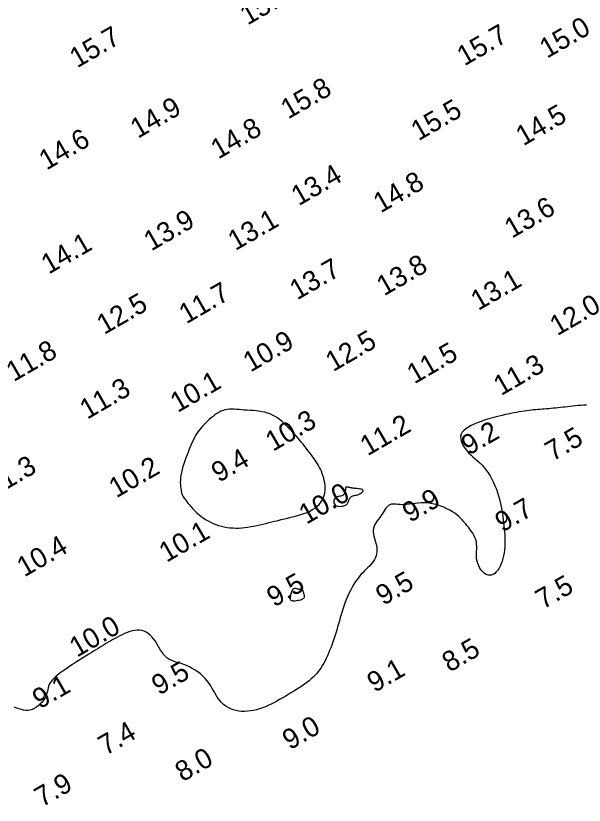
# Model space of a CAD drawing. Extents: x 3024098 to 3056816, y 418252 to 509144.
# Drawn here: x 3035040.4 to 3035182.6, y 418904.8 to 419102.3 of the extents above; entities that cross this region are included whole.
import ezdxf

# ---------------------------------------------------------------- set-up
doc = ezdxf.new("R2010")
doc.units = 0
doc.layers.add('V-CHAN-CONT-EL10', color=7, linetype='Continuous')
doc.layers.add('V-TOPO-SOUN-0911', color=7, linetype='Continuous')

msp = doc.modelspace()

# ---------------------------------------------------------------- linework, layer by layer
at = {"layer": 'V-CHAN-CONT-EL10'}
msp.add_lwpolyline([(3035183.1, 419004.9), (3035182.4, 419004.89), (3035181.71, 419004.86), (3035181.03, 419004.82), (3035180.37, 419004.76), (3035179.72, 419004.68), (3035179.08, 419004.61), (3035178.45, 419004.53), (3035177.83, 419004.45), (3035177.21, 419004.37), (3035176.61, 419004.3), (3035176.01, 419004.23), (3035175.41, 419004.18), (3035174.83, 419004.12), (3035174.25, 419004.08), (3035173.69, 419004.03), (3035173.13, 419003.98), (3035172.58, 419003.94), (3035172.04, 419003.9), (3035171.51, 419003.86), (3035170.98, 419003.81), (3035170.45, 419003.76), (3035169.91, 419003.71), (3035169.36, 419003.65), (3035168.8, 419003.59), (3035168.21, 419003.51), (3035167.61, 419003.42), (3035166.98, 419003.33), (3035166.33, 419003.23), (3035165.65, 419003.11), (3035164.96, 419002.98), (3035164.26, 419002.85), (3035163.54, 419002.7), (3035162.8, 419002.54), (3035162.05, 419002.36), (3035161.29, 419002.18), (3035160.52, 419001.98), (3035159.74, 419001.77), (3035158.96, 419001.54), (3035158.17, 419001.3), (3035157.38, 419001.04), (3035156.58, 419000.76), (3035155.79, 419000.46), (3035155.02, 419000.14), (3035154.28, 418999.8), (3035153.6, 418999.43), (3035152.99, 418999.03), (3035152.48, 418998.6), (3035152.07, 418998.14), (3035151.8, 418997.64), (3035151.67, 418997.1), (3035151.68, 418996.53), (3035151.8, 418995.94), (3035152.02, 418995.34), (3035152.34, 418994.74), (3035152.73, 418994.14), (3035153.18, 418993.56), (3035153.67, 418993), (3035154.2, 418992.47), (3035154.75, 418991.96), (3035155.31, 418991.46), (3035155.88, 418990.96), (3035156.45, 418990.44), (3035157.01, 418989.89), (3035157.56, 418989.3), (3035158.09, 418988.66), (3035158.58, 418987.96), (3035159.05, 418987.21), (3035159.49, 418986.41), (3035159.89, 418985.59), (3035160.26, 418984.75), (3035160.6, 418983.9), (3035160.9, 418983.05), (3035161.16, 418982.23), (3035161.39, 418981.43), (3035161.59, 418980.66), (3035161.75, 418979.9), (3035161.9, 418979.16), (3035162.02, 418978.43), (3035162.13, 418977.7), (3035162.23, 418976.98), (3035162.32, 418976.24), (3035162.42, 418975.5), (3035162.5, 418974.75), (3035162.58, 418974), (3035162.65, 418973.24), (3035162.71, 418972.47), (3035162.74, 418971.7), (3035162.76, 418970.94), (3035162.75, 418970.17), (3035162.71, 418969.41), (3035162.64, 418968.66), (3035162.54, 418967.92), (3035162.41, 418967.2), (3035162.25, 418966.51), (3035162.06, 418965.84), (3035161.83, 418965.22), (3035161.56, 418964.63), (3035161.27, 418964.09), (3035160.94, 418963.6), (3035160.58, 418963.18), (3035160.2, 418962.83), (3035159.8, 418962.57), (3035159.39, 418962.4), (3035158.96, 418962.34), (3035158.52, 418962.38), (3035158.08, 418962.54), (3035157.65, 418962.82), (3035157.23, 418963.18), (3035156.84, 418963.62), (3035156.48, 418964.13), (3035156.18, 418964.68), (3035155.93, 418965.27), (3035155.76, 418965.87), (3035155.66, 418966.48), (3035155.62, 418967.1), (3035155.62, 418967.71), (3035155.65, 418968.32), (3035155.68, 418968.93), (3035155.69, 418969.53), (3035155.67, 418970.12), (3035155.6, 418970.69), (3035155.45, 418971.26), (3035155.25, 418971.81), (3035154.99, 418972.34), (3035154.68, 418972.86), (3035154.34, 418973.38), (3035153.98, 418973.87), (3035153.61, 418974.36), (3035153.23, 418974.84), (3035152.85, 418975.3), (3035152.46, 418975.75), (3035152.07, 418976.2), (3035151.65, 418976.63), (3035151.21, 418977.05), (3035150.72, 418977.46), (3035150.19, 418977.87), (3035149.6, 418978.26), (3035148.94, 418978.65), (3035148.23, 418979.01), (3035147.48, 418979.36), (3035146.69, 418979.67), (3035145.88, 418979.94), (3035145.05, 418980.16), (3035144.22, 418980.33), (3035143.4, 418980.44), (3035142.59, 418980.48), (3035141.8, 418980.46), (3035141.04, 418980.4), (3035140.29, 418980.31), (3035139.58, 418980.22), (3035138.9, 418980.12), (3035138.25, 418980.04), (3035137.63, 418980), (3035137.05, 418980), (3035136.5, 418980.04), (3035136, 418980.08), (3035135.52, 418980.13), (3035135.08, 418980.16), (3035134.68, 418980.16), (3035134.3, 418980.11), (3035133.96, 418980), (3035133.64, 418979.81), (3035133.35, 418979.55), (3035133.08, 418979.24), (3035132.82, 418978.88), (3035132.56, 418978.48), (3035132.3, 418978.06), (3035132.03, 418977.63), (3035131.75, 418977.2), (3035131.44, 418976.77), (3035131.12, 418976.35), (3035130.81, 418975.93), (3035130.51, 418975.51), (3035130.25, 418975.08), (3035130.03, 418974.63), (3035129.87, 418974.17), (3035129.79, 418973.69), (3035129.79, 418973.18), (3035129.86, 418972.65), (3035129.98, 418972.1), (3035130.13, 418971.54), (3035130.3, 418970.98), (3035130.46, 418970.41), (3035130.6, 418969.85), (3035130.69, 418969.3), (3035130.73, 418968.77), (3035130.71, 418968.24), (3035130.64, 418967.74), (3035130.52, 418967.25), (3035130.34, 418966.78), (3035130.12, 418966.32), (3035129.86, 418965.88), (3035129.56, 418965.46), (3035129.23, 418965.06), (3035128.86, 418964.66), (3035128.46, 418964.26), (3035128.05, 418963.85), (3035127.62, 418963.43), (3035127.18, 418962.98), (3035126.73, 418962.5), (3035126.29, 418961.97), (3035125.84, 418961.39), (3035125.41, 418960.77), (3035124.98, 418960.1), (3035124.58, 418959.41), (3035124.18, 418958.68), (3035123.81, 418957.94), (3035123.45, 418957.18), (3035123.13, 418956.41), (3035122.82, 418955.64), (3035122.55, 418954.86), (3035122.29, 418954.09), (3035122.04, 418953.31), (3035121.81, 418952.53), (3035121.58, 418951.75), (3035121.36, 418950.97), (3035121.14, 418950.19), (3035120.91, 418949.41), (3035120.68, 418948.63), (3035120.44, 418947.86), (3035120.19, 418947.09), (3035119.94, 418946.34), (3035119.69, 418945.6), (3035119.44, 418944.87), (3035119.17, 418944.16), (3035118.91, 418943.48), (3035118.63, 418942.82), (3035118.35, 418942.17), (3035118.06, 418941.55), (3035117.77, 418940.95), (3035117.46, 418940.37), (3035117.13, 418939.82), (3035116.79, 418939.28), (3035116.44, 418938.76), (3035116.07, 418938.26), (3035115.67, 418937.78), (3035115.25, 418937.3), (3035114.8, 418936.84), (3035114.31, 418936.39), (3035113.79, 418935.95), (3035113.23, 418935.5), (3035112.64, 418935.06), (3035112, 418934.62), (3035111.33, 418934.18), (3035110.65, 418933.75), (3035109.94, 418933.32), (3035109.22, 418932.89), (3035108.5, 418932.46), (3035107.79, 418932.04), (3035107.08, 418931.63), (3035106.37, 418931.22), (3035105.67, 418930.83), (3035104.97, 418930.45), (3035104.27, 418930.09), (3035103.56, 418929.75), (3035102.84, 418929.44), (3035102.12, 418929.15), (3035101.38, 418928.9), (3035100.64, 418928.69), (3035099.89, 418928.52), (3035099.14, 418928.39), (3035098.39, 418928.3), (3035097.65, 418928.27), (3035096.91, 418928.29), (3035096.2, 418928.37), (3035095.5, 418928.51), (3035094.82, 418928.71), (3035094.17, 418928.96), (3035093.55, 418929.27), (3035092.96, 418929.63), (3035092.41, 418930.04), (3035091.9, 418930.5), (3035091.44, 418931.01), (3035091.02, 418931.55), (3035090.64, 418932.14), (3035090.28, 418932.75), (3035089.93, 418933.38), (3035089.57, 418934.02), (3035089.19, 418934.67), (3035088.77, 418935.3), (3035088.31, 418935.93), (3035087.79, 418936.53), (3035087.22, 418937.11), (3035086.6, 418937.65), (3035085.95, 418938.16), (3035085.27, 418938.63), (3035084.57, 418939.05), (3035083.86, 418939.43), (3035083.15, 418939.75), (3035082.45, 418940.01), (3035081.77, 418940.24), (3035081.1, 418940.44), (3035080.46, 418940.63), (3035079.84, 418940.83), (3035079.26, 418941.06), (3035078.72, 418941.34), (3035078.23, 418941.67), (3035077.78, 418942.08), (3035077.37, 418942.55), (3035077, 418943.07), (3035076.65, 418943.62), (3035076.31, 418944.2), (3035075.97, 418944.79), (3035075.62, 418945.37), (3035075.26, 418945.93), (3035074.87, 418946.46), (3035074.45, 418946.94), (3035074.01, 418947.38), (3035073.54, 418947.77), (3035073.05, 418948.09), (3035072.53, 418948.34), (3035071.98, 418948.52), (3035071.41, 418948.62), (3035070.81, 418948.63), (3035070.19, 418948.56), (3035069.56, 418948.43), (3035068.92, 418948.24), (3035068.28, 418948.01), (3035067.65, 418947.74), (3035067.03, 418947.45), (3035066.43, 418947.16), (3035065.84, 418946.86), (3035065.28, 418946.56), (3035064.74, 418946.26), (3035064.2, 418945.96), (3035063.68, 418945.66), (3035063.15, 418945.35), (3035062.63, 418945.04), (3035062.1, 418944.72), (3035061.56, 418944.39), (3035061, 418944.05), (3035060.44, 418943.7), (3035059.86, 418943.34), (3035059.27, 418942.97), (3035058.66, 418942.59), (3035058.03, 418942.19), (3035057.38, 418941.78), (3035056.71, 418941.35), (3035056.02, 418940.92), (3035055.33, 418940.48), (3035054.65, 418940.03), (3035053.97, 418939.58), (3035053.31, 418939.13), (3035052.67, 418938.68), (3035052.06, 418938.25), (3035051.49, 418937.83), (3035050.96, 418937.41), (3035050.48, 418937), (3035050.04, 418936.6), (3035049.65, 418936.2), (3035049.32, 418935.8), (3035049.04, 418935.4), (3035048.81, 418935), (3035048.65, 418934.6), (3035048.52, 418934.18), (3035048.42, 418933.76), (3035048.33, 418933.34), (3035048.23, 418932.9), (3035048.1, 418932.46), (3035047.93, 418932.01), (3035047.69, 418931.54), (3035047.38, 418931.07), (3035047, 418930.6), (3035046.57, 418930.15), (3035046.09, 418929.72), (3035045.58, 418929.34), (3035045.04, 418929.01), (3035044.49, 418928.76), (3035043.95, 418928.59), (3035043.41, 418928.51), (3035042.88, 418928.52), (3035042.36, 418928.59), (3035041.83, 418928.73), (3035041.28, 418928.91), (3035040.73, 418929.12), (3035040.15, 418929.35)], dxfattribs=at)
for points in [[(3035086.21, 418977.53), (3035086.76, 418977.09), (3035087.32, 418976.68), (3035087.91, 418976.29), (3035088.52, 418975.93), (3035089.14, 418975.61), (3035089.79, 418975.31), (3035090.45, 418975.05), (3035091.14, 418974.82), (3035091.84, 418974.62), (3035092.55, 418974.46), (3035093.27, 418974.33), (3035094.01, 418974.24), (3035094.75, 418974.18), (3035095.49, 418974.15), (3035096.24, 418974.16), (3035096.98, 418974.21), (3035097.73, 418974.29), (3035098.47, 418974.39), (3035099.22, 418974.51), (3035099.96, 418974.66), (3035100.71, 418974.82), (3035101.46, 418974.98), (3035102.21, 418975.16), (3035102.96, 418975.34), (3035103.72, 418975.52), (3035104.48, 418975.7), (3035105.25, 418975.89), (3035106.03, 418976.08), (3035106.81, 418976.27), (3035107.61, 418976.46), (3035108.42, 418976.66), (3035109.25, 418976.86), (3035110.08, 418977.07), (3035110.9, 418977.29), (3035111.71, 418977.53), (3035112.5, 418977.79), (3035113.26, 418978.09), (3035113.97, 418978.41), (3035114.64, 418978.77), (3035115.24, 418979.17), (3035115.78, 418979.62), (3035116.26, 418980.09), (3035116.68, 418980.6), (3035117.03, 418981.14), (3035117.32, 418981.71), (3035117.54, 418982.3), (3035117.69, 418982.91), (3035117.78, 418983.53), (3035117.81, 418984.17), (3035117.78, 418984.81), (3035117.7, 418985.44), (3035117.58, 418986.07), (3035117.43, 418986.68), (3035117.25, 418987.27), (3035117.06, 418987.83), (3035116.85, 418988.36), (3035116.62, 418988.86), (3035116.38, 418989.33), (3035116.12, 418989.79), (3035115.85, 418990.24), (3035115.57, 418990.69), (3035115.27, 418991.14), (3035114.95, 418991.6), (3035114.61, 418992.07), (3035114.26, 418992.55), (3035113.89, 418993.04), (3035113.5, 418993.55), (3035113.1, 418994.07), (3035112.69, 418994.59), (3035112.27, 418995.12), (3035111.83, 418995.66), (3035111.38, 418996.21), (3035110.92, 418996.75), (3035110.46, 418997.3), (3035109.98, 418997.84), (3035109.49, 418998.38), (3035109, 418998.91), (3035108.49, 418999.42), (3035107.98, 418999.93), (3035107.46, 419000.41), (3035106.94, 419000.87), (3035106.4, 419001.31), (3035105.84, 419001.71), (3035105.26, 419002.09), (3035104.66, 419002.42), (3035104.03, 419002.71), (3035103.38, 419002.95), (3035102.69, 419003.14), (3035101.97, 419003.28), (3035101.24, 419003.39), (3035100.5, 419003.48), (3035099.75, 419003.54), (3035099.01, 419003.59), (3035098.29, 419003.64), (3035097.58, 419003.69), (3035096.91, 419003.74), (3035096.26, 419003.81), (3035095.64, 419003.86), (3035095.04, 419003.91), (3035094.45, 419003.92), (3035093.89, 419003.91), (3035093.33, 419003.85), (3035092.79, 419003.75), (3035092.26, 419003.59), (3035091.74, 419003.37), (3035091.23, 419003.11), (3035090.72, 419002.8), (3035090.23, 419002.47), (3035089.75, 419002.11), (3035089.28, 419001.72), (3035088.82, 419001.33), (3035088.38, 419000.92), (3035087.95, 419000.51), (3035087.53, 419000.09), (3035087.13, 418999.65), (3035086.75, 418999.21), (3035086.38, 418998.75), (3035086.04, 418998.28), (3035085.71, 418997.8), (3035085.41, 418997.3), (3035085.12, 418996.78), (3035084.85, 418996.25), (3035084.58, 418995.69), (3035084.32, 418995.11), (3035084.06, 418994.5), (3035083.81, 418993.86), (3035083.54, 418993.19), (3035083.27, 418992.49), (3035082.99, 418991.76), (3035082.72, 418991.02), (3035082.46, 418990.27), (3035082.23, 418989.53), (3035082.01, 418988.79), (3035081.84, 418988.07), (3035081.71, 418987.38), (3035081.62, 418986.73), (3035081.58, 418986.11), (3035081.57, 418985.54), (3035081.59, 418985.01), (3035081.63, 418984.53), (3035081.69, 418984.1), (3035081.75, 418983.72), (3035081.8, 418983.39), (3035081.86, 418983.12), (3035081.91, 418982.9), (3035081.96, 418982.7), (3035082.03, 418982.51), (3035082.12, 418982.32), (3035082.24, 418982.11), (3035082.4, 418981.88), (3035082.6, 418981.59), (3035082.84, 418981.25), (3035083.14, 418980.85), (3035083.47, 418980.42), (3035083.85, 418979.95), (3035084.27, 418979.46), (3035084.71, 418978.97), (3035085.19, 418978.47), (3035085.69, 418977.99)], [(3035123.69, 418980.94), (3035123.75, 418981.12), (3035123.82, 418981.3), (3035123.9, 418981.47), (3035123.99, 418981.64), (3035124.09, 418981.79), (3035124.22, 418981.93), (3035124.36, 418982.05), (3035124.53, 418982.14), (3035124.73, 418982.21), (3035124.94, 418982.27), (3035125.16, 418982.33), (3035125.4, 418982.38), (3035125.65, 418982.43), (3035125.9, 418982.5), (3035126.15, 418982.59), (3035126.4, 418982.7), (3035126.64, 418982.83), (3035126.86, 418982.98), (3035127.04, 418983.12), (3035127.18, 418983.28), (3035127.26, 418983.42), (3035127.28, 418983.56), (3035127.22, 418983.68), (3035127.09, 418983.78), (3035126.88, 418983.86), (3035126.62, 418983.92), (3035126.33, 418983.97), (3035126.01, 418984.01), (3035125.69, 418984.04), (3035125.38, 418984.07), (3035125.1, 418984.09), (3035124.86, 418984.12), (3035124.66, 418984.14), (3035124.48, 418984.16), (3035124.34, 418984.19), (3035124.21, 418984.22), (3035124.09, 418984.24), (3035123.98, 418984.27), (3035123.87, 418984.3), (3035123.75, 418984.34), (3035123.63, 418984.37), (3035123.51, 418984.4), (3035123.39, 418984.42), (3035123.27, 418984.43), (3035123.17, 418984.44), (3035123.08, 418984.42), (3035123.01, 418984.4), (3035122.95, 418984.35), (3035122.92, 418984.28), (3035122.9, 418984.2), (3035122.88, 418984.09), (3035122.88, 418983.98), (3035122.87, 418983.85), (3035122.86, 418983.7), (3035122.85, 418983.54), (3035122.83, 418983.38), (3035122.79, 418983.2), (3035122.74, 418983.03), (3035122.67, 418982.85), (3035122.58, 418982.69), (3035122.46, 418982.54), (3035122.32, 418982.42), (3035122.15, 418982.31), (3035121.94, 418982.24), (3035121.71, 418982.18), (3035121.47, 418982.14), (3035121.22, 418982.09), (3035120.97, 418982.03), (3035120.73, 418981.96), (3035120.51, 418981.86), (3035120.33, 418981.71), (3035120.17, 418981.53), (3035120.06, 418981.3), (3035119.99, 418981.05), (3035119.97, 418980.79), (3035119.99, 418980.54), (3035120.06, 418980.29), (3035120.18, 418980.07), (3035120.35, 418979.89), (3035120.58, 418979.75), (3035120.85, 418979.66), (3035121.14, 418979.61), (3035121.46, 418979.59), (3035121.78, 418979.61), (3035122.09, 418979.65), (3035122.39, 418979.71), (3035122.65, 418979.78), (3035122.87, 418979.87), (3035123.05, 418979.97), (3035123.2, 418980.07), (3035123.32, 418980.19), (3035123.42, 418980.32), (3035123.5, 418980.46), (3035123.57, 418980.61), (3035123.63, 418980.77)], [(3035109.06, 418956.68), (3035109.06, 418956.5), (3035109.08, 418956.35), (3035109.14, 418956.22), (3035109.22, 418956.12), (3035109.35, 418956.05), (3035109.51, 418956), (3035109.73, 418955.98), (3035109.99, 418955.97), (3035110.28, 418955.99), (3035110.61, 418956.03), (3035110.94, 418956.08), (3035111.27, 418956.15), (3035111.59, 418956.23), (3035111.87, 418956.32), (3035112.11, 418956.42), (3035112.3, 418956.52), (3035112.44, 418956.63), (3035112.54, 418956.75), (3035112.59, 418956.88), (3035112.62, 418957.02), (3035112.61, 418957.17), (3035112.59, 418957.33), (3035112.55, 418957.51), (3035112.5, 418957.69), (3035112.45, 418957.89), (3035112.39, 418958.09), (3035112.33, 418958.28), (3035112.26, 418958.46), (3035112.19, 418958.62), (3035112.12, 418958.76), (3035112.05, 418958.87), (3035111.98, 418958.94), (3035111.92, 418958.98), (3035111.85, 418958.99), (3035111.79, 418958.98), (3035111.74, 418958.96), (3035111.69, 418958.92), (3035111.65, 418958.88), (3035111.61, 418958.85), (3035111.57, 418958.82), (3035111.54, 418958.79), (3035111.51, 418958.78), (3035111.46, 418958.77), (3035111.41, 418958.78), (3035111.35, 418958.79), (3035111.26, 418958.81), (3035111.15, 418958.85), (3035111.01, 418958.89), (3035110.85, 418958.94), (3035110.68, 418958.98), (3035110.49, 418959.01), (3035110.3, 418959.02), (3035110.11, 418959), (3035109.93, 418958.94), (3035109.77, 418958.83), (3035109.62, 418958.67), (3035109.49, 418958.46), (3035109.38, 418958.22), (3035109.28, 418957.96), (3035109.21, 418957.68), (3035109.15, 418957.41), (3035109.1, 418957.14), (3035109.07, 418956.9)]]:
    msp.add_lwpolyline(points, close=True, dxfattribs=at)

# ---------------------------------------------------------------- texts
at = {"layer": 'V-TOPO-SOUN-0911'}
for s, p in [('15.5 ', (3035098.37, 419099.88)), ('15.0 ', (3035173.26, 419091.57)), ('15.7 ', (3035055.76, 419089.18)), ('15.7 ', (3035152.61, 419089.67)), ('15.8 ', (3035108.55, 419076.38)), ('14.9 ', (3035070.95, 419071.53)), ('15.5 ', (3035141.12, 419070.94)), ('14.5 ', (3035167.33, 419069.66)), ('14.8 ', (3035091.06, 419066.35)), ('14.6 ', (3035048.11, 419063.6)), ('13.4 ', (3035111.17, 419054.67)), ('14.8 ', (3035131.68, 419052.89)), ('13.6 ', (3035164.48, 419046.53)), ('13.9 ', (3035074.3, 419043.35)), ('13.1 ', (3035095.34, 419043.46)), ('14.1 ', (3035048.65, 419037.55)), ('13.7 ', (3035110.78, 419031.11)), ('13.8 ', (3035132.53, 419032.13)), ('13.1 ', (3035156.07, 419028.47)), ('11.7 ', (3035083.09, 419025.14)), ('12.5 ', (3035062.54, 419022.45)), ('12.0 ', (3035175.82, 419022.15)), ('12.5 ', (3035119.76, 419013.16)), ('10.9 ', (3035099.13, 419013.06)), ('11.8 ', (3035039.91, 419010.67)), ('11.5 ', (3035140.1, 419010.11)), ('11.3 ', (3035161.76, 419007.16)), ('10.1 ', (3035080.91, 419002.94)), ('11.3 ', (3035058.29, 419001.25)), ('10.3 ', (3035104.74, 418993.22)), ('11.2 ', (3035128.4, 418992.1)), ('9.2', (3035153.69, 418992.24)), ('7.5', (3035174.65, 418990.76)), ('9.4', (3035091.19, 418985.45)), ('11.3 ', (3035034.73, 418981.8)), ('10.2 ', (3035065.57, 418981.57)), ('10.0 ', (3035113.09, 418974.97)), ('9.9', (3035138.99, 418975.41)), ('9.7', (3035162.12, 418973.01)), ('10.1 ', (3035078.12, 418965.44)), ('10.4 ', (3035042.57, 418961.79)), ('9.5', (3035105.03, 418954.25)), ('9.5', (3035132.32, 418954.67)), ('7.5', (3035172.25, 418953.72)), ('10.0 ', (3035055.71, 418941.7)), ('8.5', (3035148.89, 418937.97)), ('9.5', (3035076.25, 418932.2)), ('9.1', (3035130.15, 418932.9)), ('9.1', (3035046.46, 418928.77)), ('9.0', (3035108.96, 418918.52)), ('7.4', (3035062.91, 418917.14)), ('8.0', (3035082.15, 418910.54)), ('7.9', (3035046.97, 418904.21))]:
    msp.add_text(s, height=5, rotation=30, dxfattribs=at).set_placement(p)

doc.saveas('drawing.dxf')
